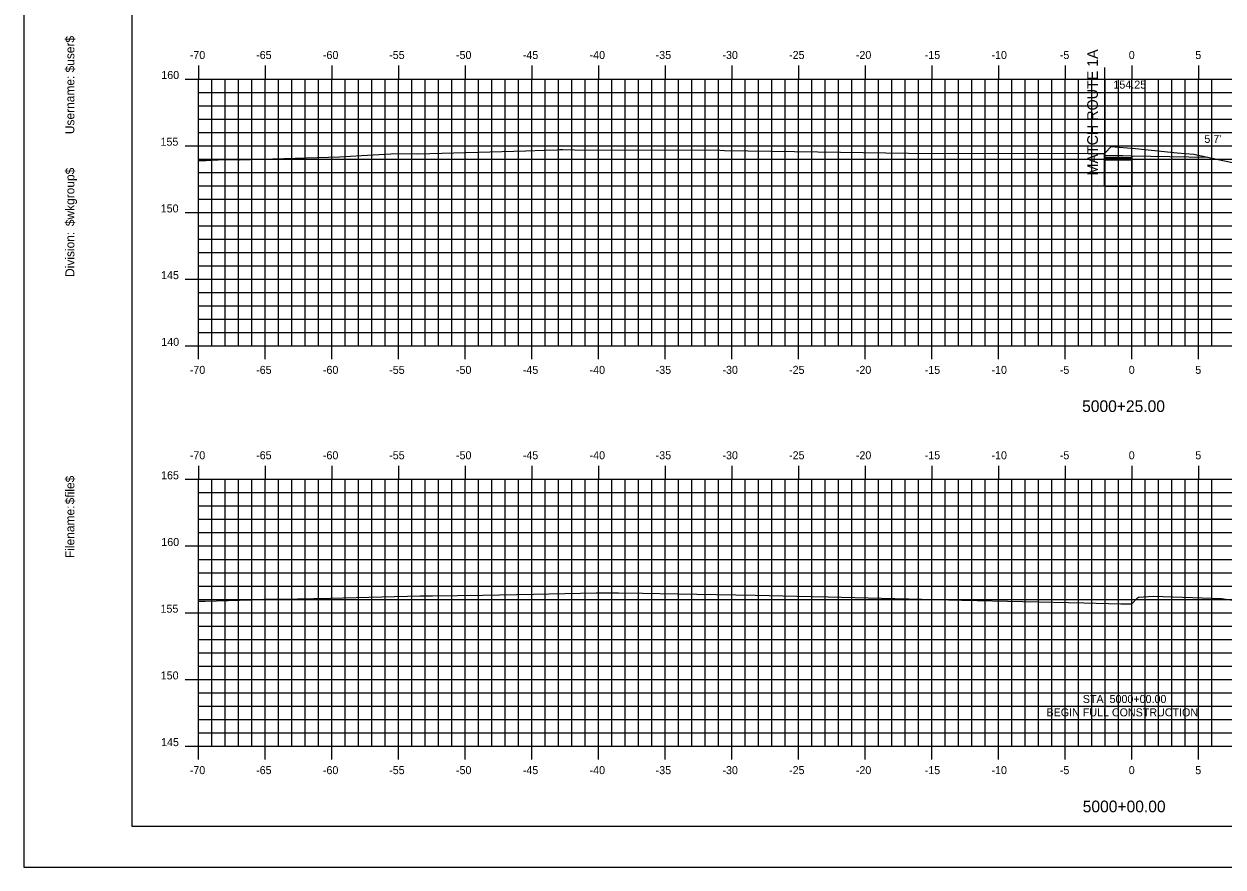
# Model space of a CAD drawing. Extents: x 850752 to 850923, y 365876 to 365986.
# Drawn here: x 850751.5 to 850841.5, y 365875.8 to 365939 of the extents above; entities that cross this region are included whole.
import ezdxf

# ---------------------------------------------------------------- set-up
doc = ezdxf.new("R2010")
doc.units = 0
for name, color, linetype in [('ANNOTATION', 7, 'Continuous'), ('BORDER', 7, 'Continuous'), ('D_Roadway_Centerline', 7, 'Continuous'), ('D_Roadway_Centerline_Text', 7, 'Continuous'), ('D_Roadway_Edge_TW', 7, 'Continuous'), ('D_Roadway_FinishedGrade', 7, 'Continuous'), ('D_Roadway_Pavement', 7, 'Continuous'), ('D_Roadway_SubGrade', 7, 'Continuous'), ('D_Text_Standard', 7, 'Continuous'), ('H_V ANNOTATION', 7, 'Continuous'), ('MAJOR', 7, 'Continuous'), ('MINOR', 7, 'Continuous'), ('PLOT BOUNDARY', 7, 'Continuous'), ('S_Roadway_Centerline', 7, 'Continuous')]:
    doc.layers.add(name, color=color, linetype=linetype)

msp = doc.modelspace()

# ---------------------------------------------------------------- linework, layer by layer
at = {"layer": 'ANNOTATION'}
msp.add_line((850832.581, 365929.103), (850832.572, 365929.262), dxfattribs=at)
at = {"layer": 'BORDER'}
msp.add_lwpolyline([(850759.629, 365878.833), (850919.629, 365878.833), (850919.629, 365983.833), (850759.629, 365983.833)], close=True, dxfattribs=at)
at = {"layer": 'D_Roadway_Centerline'}
msp.add_lwpolyline([(850832.581, 365929.103), (850833.952, 365929.088), (850834.629, 365929.081)], dxfattribs=at)
at = {"layer": 'D_Roadway_Edge_TW'}
msp.add_lwpolyline([(850832.581, 365929.103), (850834.629, 365929.081), (850834.629, 365928.914), (850832.581, 365928.936)], close=True, dxfattribs=at)
at = {"layer": 'D_Roadway_FinishedGrade'}
msp.add_line((850834.629, 365929.081), (850840.329, 365928.967), dxfattribs=at)
at = {"layer": 'D_Roadway_Pavement'}
msp.add_lwpolyline([(850832.581, 365928.936), (850834.629, 365928.914), (850834.629, 365928.748), (850832.581, 365928.769)], close=True, dxfattribs=at)
msp.add_lwpolyline([(850834.629, 365928.914), (850834.629, 365928.748)], dxfattribs=at)
msp.add_lwpolyline([(850834.629, 365928.914), (850834.629, 365928.748)], dxfattribs=at)
at = {"layer": 'D_Roadway_SubGrade'}
msp.add_line((850832.581, 365935.686), (850832.581, 365926.769), dxfattribs=at)
msp.add_lwpolyline([(850832.581, 365928.769), (850834.629, 365928.748), (850834.629, 365926.748), (850832.581, 365926.769)], close=True, dxfattribs=at)
at = {"layer": 'MAJOR'}
for p, q in [((850764.629, 365935.835), (850764.629, 365934.833)), ((850769.629, 365935.835), (850769.629, 365934.833)), ((850774.629, 365935.835), (850774.629, 365934.833)), ((850779.629, 365935.835), (850779.629, 365934.833)), ((850784.629, 365935.835), (850784.629, 365934.833)), ((850789.629, 365935.835), (850789.629, 365934.833)), ((850794.629, 365935.835), (850794.629, 365934.833)), ((850799.629, 365935.835), (850799.629, 365934.833)), ((850804.629, 365935.835), (850804.629, 365934.833)), ((850809.629, 365935.835), (850809.629, 365934.833)), ((850814.629, 365935.835), (850814.629, 365934.833)), ((850819.629, 365935.835), (850819.629, 365934.833)), ((850824.629, 365935.835), (850824.629, 365934.833)), ((850829.629, 365935.835), (850829.629, 365934.833)), ((850834.629, 365935.835), (850834.629, 365934.833)), ((850839.629, 365935.835), (850839.629, 365934.833)), ((850763.627, 365934.833), (850764.629, 365934.833)), ((850764.629, 365934.833), (850904.629, 365934.833)), ((850764.629, 365914.833), (850764.629, 365934.833)), ((850764.629, 365914.833), (850764.629, 365934.833)), ((850764.629, 365934.833), (850904.629, 365934.833)), ((850769.629, 365914.833), (850769.629, 365934.833)), ((850774.629, 365914.833), (850774.629, 365934.833)), ((850779.629, 365914.833), (850779.629, 365934.833)), ((850784.629, 365914.833), (850784.629, 365934.833)), ((850789.629, 365914.833), (850789.629, 365934.833)), ((850794.629, 365914.833), (850794.629, 365934.833)), ((850799.629, 365914.833), (850799.629, 365934.833)), ((850804.629, 365914.833), (850804.629, 365934.833)), ((850809.629, 365914.833), (850809.629, 365934.833)), ((850814.629, 365914.833), (850814.629, 365934.833)), ((850819.629, 365914.833), (850819.629, 365934.833)), ((850824.629, 365914.833), (850824.629, 365934.833)), ((850829.629, 365914.833), (850829.629, 365934.833)), ((850834.629, 365914.833), (850834.629, 365934.833)), ((850839.629, 365914.833), (850839.629, 365934.833)), ((850763.627, 365929.833), (850764.629, 365929.833)), ((850764.629, 365929.833), (850904.629, 365929.833)), ((850763.627, 365924.833), (850764.629, 365924.833)), ((850764.629, 365924.833), (850904.629, 365924.833)), ((850763.627, 365919.833), (850764.629, 365919.833)), ((850764.629, 365919.833), (850904.629, 365919.833)), ((850763.627, 365914.833), (850764.629, 365914.833)), ((850764.629, 365914.833), (850904.629, 365914.833)), ((850764.629, 365914.833), (850904.629, 365914.833)), ((850764.629, 365913.831), (850764.629, 365914.833)), ((850769.629, 365913.831), (850769.629, 365914.833)), ((850774.629, 365913.831), (850774.629, 365914.833)), ((850779.629, 365913.831), (850779.629, 365914.833)), ((850784.629, 365913.831), (850784.629, 365914.833)), ((850789.629, 365913.831), (850789.629, 365914.833)), ((850794.629, 365913.831), (850794.629, 365914.833)), ((850799.629, 365913.831), (850799.629, 365914.833)), ((850804.629, 365913.831), (850804.629, 365914.833)), ((850809.629, 365913.831), (850809.629, 365914.833)), ((850814.629, 365913.831), (850814.629, 365914.833)), ((850819.629, 365913.831), (850819.629, 365914.833)), ((850824.629, 365913.831), (850824.629, 365914.833)), ((850829.629, 365913.831), (850829.629, 365914.833)), ((850834.629, 365913.831), (850834.629, 365914.833)), ((850839.629, 365913.831), (850839.629, 365914.833)), ((850764.629, 365905.835), (850764.629, 365904.833)), ((850769.629, 365905.835), (850769.629, 365904.833)), ((850774.629, 365905.835), (850774.629, 365904.833)), ((850779.629, 365905.835), (850779.629, 365904.833)), ((850784.629, 365905.835), (850784.629, 365904.833)), ((850789.629, 365905.835), (850789.629, 365904.833)), ((850794.629, 365905.835), (850794.629, 365904.833)), ((850799.629, 365905.835), (850799.629, 365904.833)), ((850804.629, 365905.835), (850804.629, 365904.833)), ((850809.629, 365905.835), (850809.629, 365904.833)), ((850814.629, 365905.835), (850814.629, 365904.833)), ((850819.629, 365905.835), (850819.629, 365904.833)), ((850824.629, 365905.835), (850824.629, 365904.833)), ((850829.629, 365905.835), (850829.629, 365904.833)), ((850834.629, 365905.835), (850834.629, 365904.833)), ((850839.629, 365905.835), (850839.629, 365904.833)), ((850763.627, 365904.833), (850764.629, 365904.833)), ((850764.629, 365904.833), (850904.629, 365904.833)), ((850764.629, 365884.833), (850764.629, 365904.833)), ((850764.629, 365884.833), (850764.629, 365904.833)), ((850764.629, 365904.833), (850904.629, 365904.833)), ((850769.629, 365884.833), (850769.629, 365904.833)), ((850774.629, 365884.833), (850774.629, 365904.833)), ((850779.629, 365884.833), (850779.629, 365904.833)), ((850784.629, 365884.833), (850784.629, 365904.833)), ((850789.629, 365884.833), (850789.629, 365904.833)), ((850794.629, 365884.833), (850794.629, 365904.833)), ((850799.629, 365884.833), (850799.629, 365904.833)), ((850804.629, 365884.833), (850804.629, 365904.833)), ((850809.629, 365884.833), (850809.629, 365904.833)), ((850814.629, 365884.833), (850814.629, 365904.833)), ((850819.629, 365884.833), (850819.629, 365904.833)), ((850824.629, 365884.833), (850824.629, 365904.833)), ((850829.629, 365884.833), (850829.629, 365904.833)), ((850834.629, 365884.833), (850834.629, 365904.833)), ((850839.629, 365884.833), (850839.629, 365904.833)), ((850763.627, 365899.833), (850764.629, 365899.833)), ((850764.629, 365899.833), (850904.629, 365899.833)), ((850763.627, 365894.833), (850764.629, 365894.833)), ((850764.629, 365894.833), (850904.629, 365894.833)), ((850763.627, 365889.833), (850764.629, 365889.833)), ((850764.629, 365889.833), (850904.629, 365889.833)), ((850763.627, 365884.833), (850764.629, 365884.833)), ((850764.629, 365884.833), (850904.629, 365884.833)), ((850764.629, 365884.833), (850904.629, 365884.833)), ((850764.629, 365883.831), (850764.629, 365884.833)), ((850769.629, 365883.831), (850769.629, 365884.833)), ((850774.629, 365883.831), (850774.629, 365884.833)), ((850779.629, 365883.831), (850779.629, 365884.833)), ((850784.629, 365883.831), (850784.629, 365884.833)), ((850789.629, 365883.831), (850789.629, 365884.833)), ((850794.629, 365883.831), (850794.629, 365884.833)), ((850799.629, 365883.831), (850799.629, 365884.833)), ((850804.629, 365883.831), (850804.629, 365884.833)), ((850809.629, 365883.831), (850809.629, 365884.833)), ((850814.629, 365883.831), (850814.629, 365884.833)), ((850819.629, 365883.831), (850819.629, 365884.833)), ((850824.629, 365883.831), (850824.629, 365884.833)), ((850829.629, 365883.831), (850829.629, 365884.833)), ((850834.629, 365883.831), (850834.629, 365884.833)), ((850839.629, 365883.831), (850839.629, 365884.833))]:
    msp.add_line(p, q, dxfattribs=at)
at = {"layer": 'MINOR'}
for p, q in [((850765.629, 365914.833), (850765.629, 365934.833)), ((850766.629, 365914.833), (850766.629, 365934.833)), ((850767.629, 365914.833), (850767.629, 365934.833)), ((850768.629, 365914.833), (850768.629, 365934.833)), ((850770.629, 365914.833), (850770.629, 365934.833)), ((850771.629, 365914.833), (850771.629, 365934.833)), ((850772.629, 365914.833), (850772.629, 365934.833)), ((850773.629, 365914.833), (850773.629, 365934.833)), ((850775.629, 365914.833), (850775.629, 365934.833)), ((850776.629, 365914.833), (850776.629, 365934.833)), ((850777.629, 365914.833), (850777.629, 365934.833)), ((850778.629, 365914.833), (850778.629, 365934.833)), ((850780.629, 365914.833), (850780.629, 365934.833)), ((850781.629, 365914.833), (850781.629, 365934.833)), ((850782.629, 365914.833), (850782.629, 365934.833)), ((850783.629, 365914.833), (850783.629, 365934.833)), ((850785.629, 365914.833), (850785.629, 365934.833)), ((850786.629, 365914.833), (850786.629, 365934.833)), ((850787.629, 365914.833), (850787.629, 365934.833)), ((850788.629, 365914.833), (850788.629, 365934.833)), ((850790.629, 365914.833), (850790.629, 365934.833)), ((850791.629, 365914.833), (850791.629, 365934.833)), ((850792.629, 365914.833), (850792.629, 365934.833)), ((850793.629, 365914.833), (850793.629, 365934.833)), ((850795.629, 365914.833), (850795.629, 365934.833)), ((850796.629, 365914.833), (850796.629, 365934.833)), ((850797.629, 365914.833), (850797.629, 365934.833)), ((850798.629, 365914.833), (850798.629, 365934.833)), ((850800.629, 365914.833), (850800.629, 365934.833)), ((850801.629, 365914.833), (850801.629, 365934.833)), ((850802.629, 365914.833), (850802.629, 365934.833)), ((850803.629, 365914.833), (850803.629, 365934.833)), ((850805.629, 365914.833), (850805.629, 365934.833)), ((850806.629, 365914.833), (850806.629, 365934.833)), ((850807.629, 365914.833), (850807.629, 365934.833)), ((850808.629, 365914.833), (850808.629, 365934.833)), ((850810.629, 365914.833), (850810.629, 365934.833)), ((850811.629, 365914.833), (850811.629, 365934.833)), ((850812.629, 365914.833), (850812.629, 365934.833)), ((850813.629, 365914.833), (850813.629, 365934.833)), ((850815.629, 365914.833), (850815.629, 365934.833)), ((850816.629, 365914.833), (850816.629, 365934.833)), ((850817.629, 365914.833), (850817.629, 365934.833)), ((850818.629, 365914.833), (850818.629, 365934.833)), ((850820.629, 365914.833), (850820.629, 365934.833)), ((850821.629, 365914.833), (850821.629, 365934.833)), ((850822.629, 365914.833), (850822.629, 365934.833)), ((850823.629, 365914.833), (850823.629, 365934.833)), ((850825.629, 365914.833), (850825.629, 365934.833)), ((850826.629, 365914.833), (850826.629, 365934.833)), ((850827.629, 365914.833), (850827.629, 365934.833)), ((850828.629, 365914.833), (850828.629, 365934.833)), ((850830.629, 365914.833), (850830.629, 365934.833)), ((850831.629, 365914.833), (850831.629, 365934.833)), ((850832.629, 365914.833), (850832.629, 365934.833)), ((850833.629, 365914.833), (850833.629, 365934.833)), ((850835.629, 365914.833), (850835.629, 365934.833)), ((850836.629, 365914.833), (850836.629, 365934.833)), ((850837.629, 365914.833), (850837.629, 365934.833)), ((850838.629, 365914.833), (850838.629, 365934.833)), ((850840.629, 365914.833), (850840.629, 365934.833)), ((850764.629, 365933.833), (850904.629, 365933.833)), ((850764.629, 365933.833), (850765.631, 365933.833)), ((850764.629, 365932.833), (850904.629, 365932.833)), ((850764.629, 365932.833), (850765.631, 365932.833)), ((850764.629, 365931.833), (850904.629, 365931.833)), ((850764.629, 365931.833), (850765.631, 365931.833)), ((850764.629, 365930.833), (850904.629, 365930.833)), ((850764.629, 365930.833), (850765.631, 365930.833)), ((850764.629, 365928.833), (850904.629, 365928.833)), ((850764.629, 365928.833), (850765.631, 365928.833)), ((850764.629, 365927.833), (850904.629, 365927.833)), ((850764.629, 365927.833), (850765.631, 365927.833)), ((850764.629, 365926.833), (850904.629, 365926.833)), ((850764.629, 365926.833), (850765.631, 365926.833)), ((850764.629, 365925.833), (850904.629, 365925.833)), ((850764.629, 365925.833), (850765.631, 365925.833)), ((850764.629, 365923.833), (850904.629, 365923.833)), ((850764.629, 365923.833), (850765.631, 365923.833)), ((850764.629, 365922.833), (850904.629, 365922.833)), ((850764.629, 365922.833), (850765.631, 365922.833)), ((850764.629, 365921.833), (850904.629, 365921.833)), ((850764.629, 365921.833), (850765.631, 365921.833)), ((850764.629, 365920.833), (850904.629, 365920.833)), ((850764.629, 365920.833), (850765.631, 365920.833)), ((850764.629, 365918.833), (850904.629, 365918.833)), ((850764.629, 365918.833), (850765.631, 365918.833)), ((850764.629, 365917.833), (850904.629, 365917.833)), ((850764.629, 365917.833), (850765.631, 365917.833)), ((850764.629, 365916.833), (850904.629, 365916.833)), ((850764.629, 365916.833), (850765.631, 365916.833)), ((850764.629, 365915.833), (850904.629, 365915.833)), ((850764.629, 365915.833), (850765.631, 365915.833)), ((850765.629, 365884.833), (850765.629, 365904.833)), ((850766.629, 365884.833), (850766.629, 365904.833)), ((850767.629, 365884.833), (850767.629, 365904.833)), ((850768.629, 365884.833), (850768.629, 365904.833)), ((850770.629, 365884.833), (850770.629, 365904.833)), ((850771.629, 365884.833), (850771.629, 365904.833)), ((850772.629, 365884.833), (850772.629, 365904.833)), ((850773.629, 365884.833), (850773.629, 365904.833)), ((850775.629, 365884.833), (850775.629, 365904.833)), ((850776.629, 365884.833), (850776.629, 365904.833)), ((850777.629, 365884.833), (850777.629, 365904.833)), ((850778.629, 365884.833), (850778.629, 365904.833)), ((850780.629, 365884.833), (850780.629, 365904.833)), ((850781.629, 365884.833), (850781.629, 365904.833)), ((850782.629, 365884.833), (850782.629, 365904.833)), ((850783.629, 365884.833), (850783.629, 365904.833)), ((850785.629, 365884.833), (850785.629, 365904.833)), ((850786.629, 365884.833), (850786.629, 365904.833)), ((850787.629, 365884.833), (850787.629, 365904.833)), ((850788.629, 365884.833), (850788.629, 365904.833)), ((850790.629, 365884.833), (850790.629, 365904.833)), ((850791.629, 365884.833), (850791.629, 365904.833)), ((850792.629, 365884.833), (850792.629, 365904.833)), ((850793.629, 365884.833), (850793.629, 365904.833)), ((850795.629, 365884.833), (850795.629, 365904.833)), ((850796.629, 365884.833), (850796.629, 365904.833)), ((850797.629, 365884.833), (850797.629, 365904.833)), ((850798.629, 365884.833), (850798.629, 365904.833)), ((850800.629, 365884.833), (850800.629, 365904.833)), ((850801.629, 365884.833), (850801.629, 365904.833)), ((850802.629, 365884.833), (850802.629, 365904.833)), ((850803.629, 365884.833), (850803.629, 365904.833)), ((850805.629, 365884.833), (850805.629, 365904.833)), ((850806.629, 365884.833), (850806.629, 365904.833)), ((850807.629, 365884.833), (850807.629, 365904.833)), ((850808.629, 365884.833), (850808.629, 365904.833)), ((850810.629, 365884.833), (850810.629, 365904.833)), ((850811.629, 365884.833), (850811.629, 365904.833)), ((850812.629, 365884.833), (850812.629, 365904.833)), ((850813.629, 365884.833), (850813.629, 365904.833)), ((850815.629, 365884.833), (850815.629, 365904.833)), ((850816.629, 365884.833), (850816.629, 365904.833)), ((850817.629, 365884.833), (850817.629, 365904.833)), ((850818.629, 365884.833), (850818.629, 365904.833)), ((850820.629, 365884.833), (850820.629, 365904.833)), ((850821.629, 365884.833), (850821.629, 365904.833)), ((850822.629, 365884.833), (850822.629, 365904.833)), ((850823.629, 365884.833), (850823.629, 365904.833)), ((850825.629, 365884.833), (850825.629, 365904.833)), ((850826.629, 365884.833), (850826.629, 365904.833)), ((850827.629, 365884.833), (850827.629, 365904.833)), ((850828.629, 365884.833), (850828.629, 365904.833)), ((850830.629, 365884.833), (850830.629, 365904.833)), ((850831.629, 365884.833), (850831.629, 365904.833)), ((850832.629, 365884.833), (850832.629, 365904.833)), ((850833.629, 365884.833), (850833.629, 365904.833)), ((850835.629, 365884.833), (850835.629, 365904.833)), ((850836.629, 365884.833), (850836.629, 365904.833)), ((850837.629, 365884.833), (850837.629, 365904.833)), ((850838.629, 365884.833), (850838.629, 365904.833)), ((850840.629, 365884.833), (850840.629, 365904.833)), ((850764.629, 365903.833), (850904.629, 365903.833)), ((850764.629, 365903.833), (850765.631, 365903.833)), ((850764.629, 365902.833), (850904.629, 365902.833)), ((850764.629, 365902.833), (850765.631, 365902.833)), ((850764.629, 365901.833), (850904.629, 365901.833)), ((850764.629, 365901.833), (850765.631, 365901.833)), ((850764.629, 365900.833), (850904.629, 365900.833)), ((850764.629, 365900.833), (850765.631, 365900.833)), ((850764.629, 365898.833), (850904.629, 365898.833)), ((850764.629, 365898.833), (850765.631, 365898.833)), ((850764.629, 365897.833), (850904.629, 365897.833)), ((850764.629, 365897.833), (850765.631, 365897.833)), ((850764.629, 365896.833), (850904.629, 365896.833)), ((850764.629, 365896.833), (850765.631, 365896.833)), ((850764.629, 365895.833), (850904.629, 365895.833)), ((850764.629, 365895.833), (850765.631, 365895.833)), ((850764.629, 365893.833), (850904.629, 365893.833)), ((850764.629, 365893.833), (850765.631, 365893.833)), ((850764.629, 365892.833), (850904.629, 365892.833)), ((850764.629, 365892.833), (850765.631, 365892.833)), ((850764.629, 365891.833), (850904.629, 365891.833)), ((850764.629, 365891.833), (850765.631, 365891.833)), ((850764.629, 365890.833), (850904.629, 365890.833)), ((850764.629, 365890.833), (850765.631, 365890.833)), ((850764.629, 365888.833), (850904.629, 365888.833)), ((850764.629, 365888.833), (850765.631, 365888.833)), ((850764.629, 365887.833), (850904.629, 365887.833)), ((850764.629, 365887.833), (850765.631, 365887.833)), ((850764.629, 365886.833), (850904.629, 365886.833)), ((850764.629, 365886.833), (850765.631, 365886.833)), ((850764.629, 365885.833), (850904.629, 365885.833)), ((850764.629, 365885.833), (850765.631, 365885.833))]:
    msp.add_line(p, q, dxfattribs=at)
at = {"layer": 'PLOT BOUNDARY'}
msp.add_lwpolyline([(850751.536, 365875.774), (850921.536, 365875.774), (850921.536, 365985.774), (850751.536, 365985.774)], close=True, dxfattribs=at)
at = {"layer": 'S_Roadway_Centerline'}
for points in [[(850764.629, 365928.718), (850765.165, 365928.734), (850766.554, 365928.803), (850767.614, 365928.778), (850767.688, 365928.779), (850775.188, 365929.005), (850776.852, 365929.092), (850779.055, 365929.233), (850779.173, 365929.251), (850781.077, 365929.223), (850789.178, 365929.453), (850790.549, 365929.503), (850791.521, 365929.536), (850791.685, 365929.542), (850791.949, 365929.539), (850792.822, 365929.535), (850803.724, 365929.49), (850804.064, 365929.474), (850811.083, 365929.379), (850817.868, 365929.274), (850831.336, 365929.245), (850832.572, 365929.262), (850832.617, 365929.306), (850833.079, 365929.768), (850834.901, 365929.63), (850838.019, 365929.305), (850839.259, 365929.192), (850841.227, 365928.777), (850846.397, 365927.684)], [(850764.629, 365895.703), (850764.763, 365895.707), (850765.121, 365895.687), (850769.426, 365895.833), (850769.514, 365895.836), (850769.532, 365895.836), (850769.586, 365895.837), (850770.799, 365895.853), (850774.534, 365895.912), (850781.26, 365896.086), (850782.087, 365896.105), (850782.175, 365896.11), (850785.931, 365896.16), (850789.74, 365896.234), (850794.441, 365896.326), (850796.114, 365896.313), (850797.91, 365896.289), (850800.538, 365896.247), (850806.366, 365896.153), (850809.507, 365896.068), (850811.836, 365896.013), (850821.874, 365895.774), (850831.029, 365895.563), (850833.789, 365895.505), (850834.629, 365895.509), (850835.057, 365895.937), (850835.129, 365896.009), (850836.241, 365896.063), (850841.333, 365895.907), (850843.206, 365895.619)]]:
    msp.add_lwpolyline(points, dxfattribs=at)

# ---------------------------------------------------------------- texts
at = {"layer": 'ANNOTATION'}
msp.add_text('MATCH ROUTE 1A', height=0.8, rotation=90, dxfattribs=at).set_placement((850832.074, 365927.604))
for s, p in [('STA. 5000+00.00 ', (850830.945, 365888.068)), ('BEGIN FULL CONSTRUCTION', (850828.22, 365887.066))]:
    msp.add_text(s, height=0.6, dxfattribs=at).set_placement(p)
at = {"layer": 'BORDER'}
for s, p in [('$user$', (850755.314, 365935.325)), ('Username:', (850755.314, 365930.701)), ('$wkgroup$', (850755.314, 365923.803)), ('Division:', (850755.314, 365919.999)), ('$file$', (850755.314, 365902.959)), ('Filename:', (850755.314, 365898.932))]:
    msp.add_text(s, height=0.6696, rotation=90, dxfattribs=at).set_placement(p)
at = {"layer": 'D_Roadway_Centerline_Text'}
msp.add_text('154.25', height=0.6, dxfattribs=at).set_placement((850833.24, 365934.113))
at = {"layer": 'D_Text_Standard'}
msp.add_text("5.7'", height=0.6, dxfattribs=at).set_placement((850840.06, 365930.044))
at = {"layer": 'H_V ANNOTATION'}
for s, height, p in [('-70', 0.6, (850763.97, 365936.333)), ('-65', 0.6, (850768.946, 365936.333)), ('-60', 0.6, (850773.954, 365936.333)), ('-55', 0.6, (850778.925, 365936.333)), ('-50', 0.6, (850783.933, 365936.333)), ('-45', 0.6, (850788.946, 365936.333)), ('-40', 0.6, (850793.954, 365936.333)), ('-35', 0.6, (850798.909, 365936.333)), ('-30', 0.6, (850803.917, 365936.333)), ('-25', 0.6, (850808.914, 365936.333)), ('-20', 0.6, (850813.922, 365936.333)), ('-15', 0.6, (850819.086, 365936.333)), ('-10', 0.6, (850824.094, 365936.333)), ('-5', 0.6, (850829.219, 365936.333)), ('0', 0.6, (850834.388, 365936.333)), ('5', 0.6, (850839.38, 365936.333)), ('160', 0.6, (850761.834, 365934.833)), ('155', 0.6, (850761.775, 365929.833)), ('150', 0.6, (850761.791, 365924.833)), ('145', 0.6, (850761.818, 365919.833)), ('140', 0.6, (850761.834, 365914.833)), ('-70', 0.6, (850763.97, 365912.733)), ('-65', 0.6, (850768.946, 365912.733)), ('-60', 0.6, (850773.954, 365912.733)), ('-55', 0.6, (850778.925, 365912.733)), ('-50', 0.6, (850783.933, 365912.733)), ('-45', 0.6, (850788.946, 365912.733)), ('-40', 0.6, (850793.954, 365912.733)), ('-35', 0.6, (850798.909, 365912.733)), ('-30', 0.6, (850803.917, 365912.733)), ('-25', 0.6, (850808.914, 365912.733)), ('-20', 0.6, (850813.922, 365912.733)), ('-15', 0.6, (850819.086, 365912.733)), ('-10', 0.6, (850824.094, 365912.733)), ('-5', 0.6, (850829.219, 365912.733)), ('0', 0.6, (850834.388, 365912.733)), ('5', 0.6, (850839.38, 365912.733)), ('5000+25.00', 0.875, (850830.891, 365909.876)), ('-70', 0.6, (850763.97, 365906.333)), ('-65', 0.6, (850768.946, 365906.333)), ('-60', 0.6, (850773.954, 365906.333)), ('-55', 0.6, (850778.925, 365906.333)), ('-50', 0.6, (850783.933, 365906.333)), ('-45', 0.6, (850788.946, 365906.333)), ('-40', 0.6, (850793.954, 365906.333)), ('-35', 0.6, (850798.909, 365906.333)), ('-30', 0.6, (850803.917, 365906.333)), ('-25', 0.6, (850808.914, 365906.333)), ('-20', 0.6, (850813.922, 365906.333)), ('-15', 0.6, (850819.086, 365906.333)), ('-10', 0.6, (850824.094, 365906.333)), ('-5', 0.6, (850829.219, 365906.333)), ('0', 0.6, (850834.388, 365906.333)), ('5', 0.6, (850839.38, 365906.333)), ('165', 0.6, (850761.818, 365904.833)), ('160', 0.6, (850761.834, 365899.833)), ('155', 0.6, (850761.775, 365894.833)), ('150', 0.6, (850761.791, 365889.833)), ('145', 0.6, (850761.818, 365884.833)), ('-70', 0.6, (850763.97, 365882.733)), ('-65', 0.6, (850768.946, 365882.733)), ('-60', 0.6, (850773.954, 365882.733)), ('-55', 0.6, (850778.925, 365882.733)), ('-50', 0.6, (850783.933, 365882.733)), ('-45', 0.6, (850788.946, 365882.733)), ('-40', 0.6, (850793.954, 365882.733)), ('-35', 0.6, (850798.909, 365882.733)), ('-30', 0.6, (850803.917, 365882.733)), ('-25', 0.6, (850808.914, 365882.733)), ('-20', 0.6, (850813.922, 365882.733)), ('-15', 0.6, (850819.086, 365882.733)), ('-10', 0.6, (850824.094, 365882.733)), ('-5', 0.6, (850829.219, 365882.733)), ('0', 0.6, (850834.388, 365882.733)), ('5', 0.6, (850839.38, 365882.733)), ('5000+00.00', 0.875, (850830.938, 365879.876))]:
    msp.add_text(s, height=height, dxfattribs=at).set_placement(p)
at = {"layer": 'MAJOR'}
for p in [(850764.624, 365914.833), (850764.624, 365884.833)]:
    msp.add_text('-', height=0.006, dxfattribs=at).set_placement(p)

doc.saveas('drawing.dxf')
